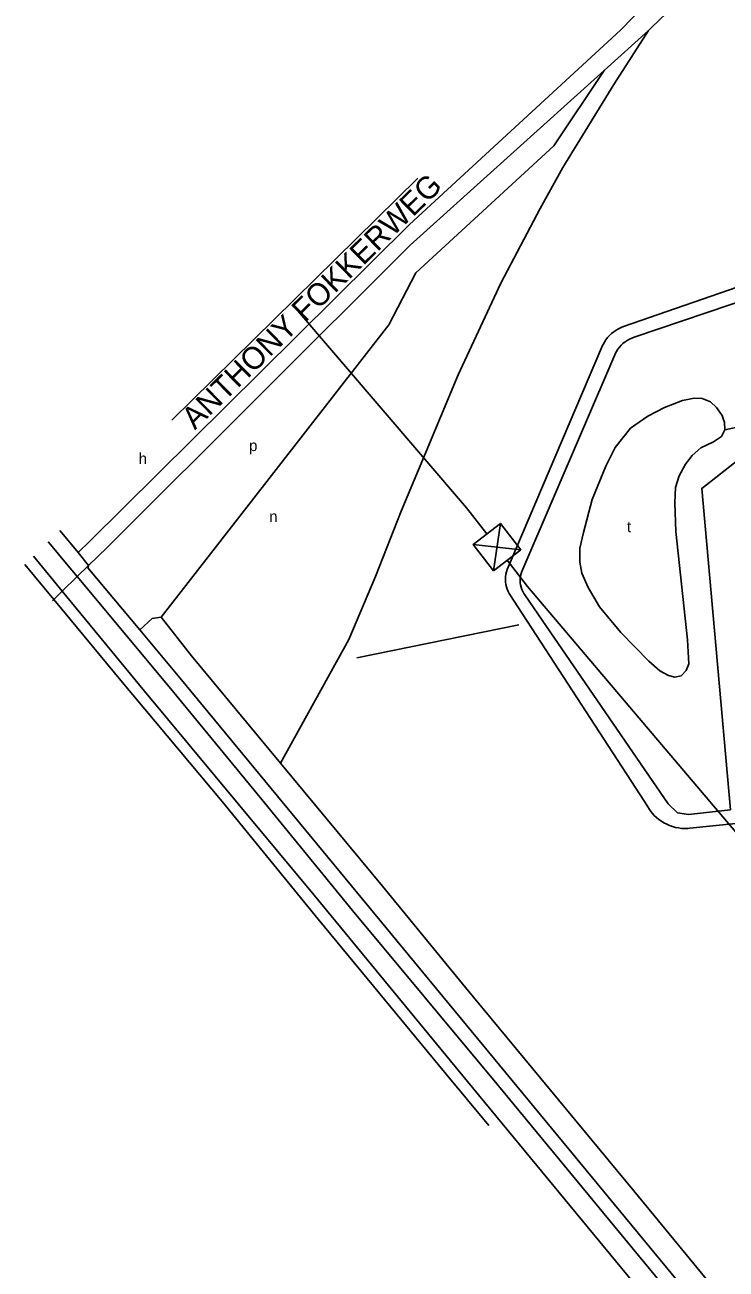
# Model space of a CAD drawing. Extents: x 158142 to 159655, y 385262 to 387204.
# Drawn here: x 158141.7 to 158393.2, y 386403.5 to 386850.2 of the extents above; entities that cross this region are included whole.
import ezdxf

# ---------------------------------------------------------------- set-up
doc = ezdxf.new("R2010")
doc.units = 0
for name, color, linetype in [('BLT_Basislijn', 7, 'Continuous'), ('BLT_Centroide', 7, 'Continuous'), ('BLT_Hoogspanningsmast_en_leidingen', 7, 'Continuous'), ('BLT_Spoorlijn', 7, 'Continuous'), ('BLT_Straatnaam_hoofdweg', 7, 'Continuous'), ('BLT_Vlakafsluiter', 7, 'Continuous')]:
    doc.layers.add(name, color=color, linetype=linetype)

msp = doc.modelspace()

# ---------------------------------------------------------------- linework, layer by layer
at = {"layer": 'BLT_Basislijn'}
for p, q in [((158279.64, 386778.57), (158355.28, 386848.37)), ((158349.41, 386833.89), (158365.31, 386848.23)), ((158279.91, 386771.19), (158349.41, 386833.89)), ((158360.27, 386738.05), (158545.3, 386801.11)), ((158194.37, 386708.36), (158282.57, 386795.15)), ((158171.76, 386663.23), (158279.91, 386771.19)), ((158418.09, 386763.39), (158356.45, 386741.94)), ((158348.88, 386735.08), (158315.42, 386656.37)), ((158319.95, 386653.97), (158353.26, 386731.75)), ((158154.31, 386668.67), (158154.26, 386668.63)), ((158154.26, 386668.63), (158154.26, 386668.63)), ((158154.26, 386668.63), (158160.74, 386660.75)), ((158160.74, 386660.75), (158164.52, 386656.14)), ((158164.52, 386656.14), (158171.12, 386662.6)), ((158171.12, 386662.6), (158171.76, 386663.23)), ((158363.98, 386571.33), (158315.39, 386646.02)), ((158321.01, 386645.61), (158327.22, 386636.55)), ((158260.72, 386622.93), (158318.89, 386634.81)), ((158327.22, 386636.55), (158372.47, 386570.52)), ((158269.98, 386540.93), (158233.37, 386585.11)), ((158363.98, 386571.33), (158365.99, 386568.12)), ((158299.7, 386504.62), (158269.98, 386540.93)), ((158360.07, 386431.65), (158299.7, 386504.62)), ((158360.07, 386431.65), (158423.26, 386354.85))]:
    msp.add_line(p, q, dxfattribs=at)
for points in [[(158365.31, 386848.23), (158366.35, 386849.16), (158439.42, 386919.27), (158470.86, 386949.22), (158484.7, 386962.23)], [(158377.52, 386871.37), (158355.28, 386848.37)], [(158233.37, 386585.11), (158257.82, 386629.6), (158267.45, 386652.13), (158276.64, 386675.62), (158284.4, 386694.18), (158297.1, 386724.54), (158312.43, 386757.54), (158326.46, 386784.3), (158334.61, 386799.01), (158352.94, 386828.87), (158365.31, 386848.23)], [(158190.59, 386637.57), (158272.17, 386742.51), (158281.87, 386761.23), (158331.46, 386806.8), (158349.41, 386833.89)], [(158164.91, 386664.81), (158226.14, 386725.6), (158279.64, 386778.57)], [(158516.25, 386777.61), (158397.21, 386705.81), (158392.71, 386704.81)], [(158356.45, 386741.94), (158355.5, 386741.58), (158354.59, 386741.15), (158353.71, 386740.64), (158352.88, 386740.07), (158352.1, 386739.43), (158351.36, 386738.74), (158350.69, 386737.99), (158350.08, 386737.18), (158349.53, 386736.33), (158349.05, 386735.44), (158348.88, 386735.08)], [(158360.27, 386738.05), (158359.39, 386737.76), (158358.54, 386737.39), (158357.72, 386736.95), (158356.94, 386736.44), (158356.21, 386735.86), (158355.54, 386735.23), (158354.92, 386734.54), (158354.36, 386733.8), (158353.87, 386733.01), (158353.45, 386732.18), (158353.26, 386731.75)], [(158378.83, 386618.37), (158377.05, 386616.52), (158374.82, 386616.05), (158372.55, 386616.59), (158369.47, 386618.25), (158365.49, 386621.77), (158355.38, 386632.06), (158347.82, 386641.3), (158343.67, 386648.22), (158341.39, 386653.39), (158340.74, 386657.33), (158340.69, 386662.35), (158342, 386668.03), (158345.2, 386679.77), (158350.07, 386691.85), (158353.44, 386698.5), (158358.94, 386705.43), (158365.14, 386709.71), (158371.07, 386712.83), (158377.51, 386715.32), (158381.73, 386716.19), (158384.59, 386716.07), (158387.57, 386714.85), (158389.78, 386712.86), (158391.82, 386709.98), (158392.59, 386707.47), (158392.71, 386704.81)], [(158392.71, 386704.81), (158391.55, 386702.45), (158388.64, 386700.55), (158384.18, 386698.32), (158380.97, 386695.64), (158378.58, 386692.45), (158376.33, 386688.28), (158375.04, 386684.12), (158374.78, 386678.65), (158375.22, 386668.31), (158379.34, 386629.4), (158379.82, 386620.76), (158378.83, 386618.37)], [(158404.59, 386699.52), (158384.48, 386683.83), (158394.81, 386568.41)], [(158160.74, 386660.75), (158164.91, 386664.81)], [(158164.52, 386656.14), (158164.27, 386655.34), (158182.92, 386632.97)], [(158315.42, 386656.37), (158315, 386655.57), (158314.65, 386654.73), (158314.38, 386653.86), (158314.18, 386652.97), (158314.06, 386652.06), (158314.02, 386651.15), (158314.06, 386650.24), (158314.18, 386649.34), (158314.38, 386648.45), (158314.66, 386647.58), (158315.01, 386646.74), (158315.39, 386646.02)], [(158319.95, 386653.97), (158319.67, 386653.2), (158319.46, 386652.4), (158319.34, 386651.59), (158319.29, 386650.77), (158319.33, 386649.95), (158319.44, 386649.14), (158319.63, 386648.34), (158319.9, 386647.56), (158320.25, 386646.82), (158320.66, 386646.11), (158321.01, 386645.61)], [(158190.59, 386637.57), (158187.26, 386637.07), (158182.92, 386632.97)], [(158233.37, 386585.11), (158201.42, 386623.67), (158190.59, 386637.57)], [(158182.92, 386632.97), (158197.27, 386615.74), (158375.75, 386399.25)], [(158379.66, 386566.76), (158375.75, 386567.34), (158372.47, 386570.52)], [(158365.99, 386568.12), (158366.68, 386567.24), (158367.42, 386566.41), (158368.22, 386565.64), (158369.07, 386564.93), (158369.97, 386564.28), (158370.91, 386563.7), (158371.9, 386563.19), (158372.92, 386562.75), (158373.96, 386562.38), (158375.04, 386562.09), (158376.13, 386561.88), (158377.23, 386561.75), (158378.34, 386561.7), (158379.45, 386561.73), (158380.16, 386561.79)], [(158394.81, 386568.41), (158379.66, 386566.76)], [(158478.8, 386457.87), (158445.93, 386497.1), (158411.14, 386537.58), (158406.37, 386545.08), (158404.4, 386548.95), (158400.11, 386561.45), (158399.13, 386562.67), (158398.2, 386563.31), (158396.7, 386563.44), (158380.16, 386561.79)]]:
    msp.add_lwpolyline(points, dxfattribs=at)
at = {"layer": 'BLT_Hoogspanningsmast_en_leidingen'}
for p, q in [((158238.08, 386749.29), (158300.04, 386676.88)), ((158307.34, 386667.44), (158300.04, 386676.88)), ((158312.21, 386671.21), (158309.79, 386654.24)), ((158302.48, 386663.67), (158319.52, 386661.78)), ((158321.96, 386648.57), (158314.65, 386658.01)), ((158321.96, 386648.57), (158459.79, 386485.85))]:
    msp.add_line(p, q, dxfattribs=at)
msp.add_lwpolyline([(158309.79, 386654.24), (158319.52, 386661.78), (158312.21, 386671.21), (158302.48, 386663.67)], close=True, dxfattribs=at)
at = {"layer": 'BLT_Spoorlijn'}
for p, q in [((158141.66, 386656.5), (158152.04, 386643.93)), ((158144.69, 386659.42), (158155.03, 386646.85)), ((158156.6, 386656.73), (158160.43, 386652.14)), ((158160.43, 386652.14), (158193.43, 386612.54)), ((158155.03, 386646.85), (158184.51, 386610.98)), ((158152.04, 386643.93), (158176.68, 386614.11))]:
    msp.add_line(p, q, dxfattribs=at)
for points in [[(158150.05, 386664.58), (158150.82, 386663.67)], [(158150.82, 386663.67), (158156.6, 386656.73)], [(158176.68, 386614.11), (158212.38, 386571.33)], [(158184.51, 386610.98), (158218.17, 386570.55)], [(158193.43, 386612.54), (158226.65, 386572.11)], [(158212.38, 386571.33), (158246.83, 386529.09)], [(158218.17, 386570.55), (158245.42, 386537.7)], [(158226.65, 386572.11), (158259.18, 386532.22)], [(158245.42, 386537.7), (158300.48, 386470.82)], [(158259.18, 386532.22), (158310.97, 386470.04)], [(158246.83, 386529.09), (158292.8, 386473.49)], [(158292.8, 386473.49), (158308.06, 386455.08)], [(158300.48, 386470.82), (158362.03, 386396.22)], [(158310.97, 386470.04), (158371.9, 386396.06)]]:
    msp.add_lwpolyline(points, dxfattribs=at)
at = {"layer": 'BLT_Vlakafsluiter'}
for p, q in [((158164.52, 386656.14), (158160.43, 386652.14)), ((158160.43, 386652.14), (158155.03, 386646.85)), ((158155.03, 386646.85), (158152.04, 386643.93)), ((158152.04, 386643.93), (158151.59, 386643.48))]:
    msp.add_line(p, q, dxfattribs=at)

# ---------------------------------------------------------------- texts
at = {"layer": 'BLT_Centroide'}
for s, p in [('p', (158222.08, 386697.21)), ('h', (158182.49, 386692.51)), ('n', (158229.29, 386671.75)), ('t', (158357.65, 386668.06))]:
    msp.add_text(s, height=4, dxfattribs=at).set_placement(p)
at = {"layer": 'BLT_Straatnaam_hoofdweg'}
msp.add_text('ANTHONY FOKKERWEG', height=7.9999, rotation=44.3851, dxfattribs=at).set_placement((158202.67, 386704.55))

doc.saveas('drawing.dxf')
